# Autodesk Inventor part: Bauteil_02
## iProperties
Created: 2007-04
Part Number: Bauteil_02
Document SubType Name: Modeling
Designer: Sascha Fleischer
Author: Sascha Fleischer
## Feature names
1. Extrusion1
